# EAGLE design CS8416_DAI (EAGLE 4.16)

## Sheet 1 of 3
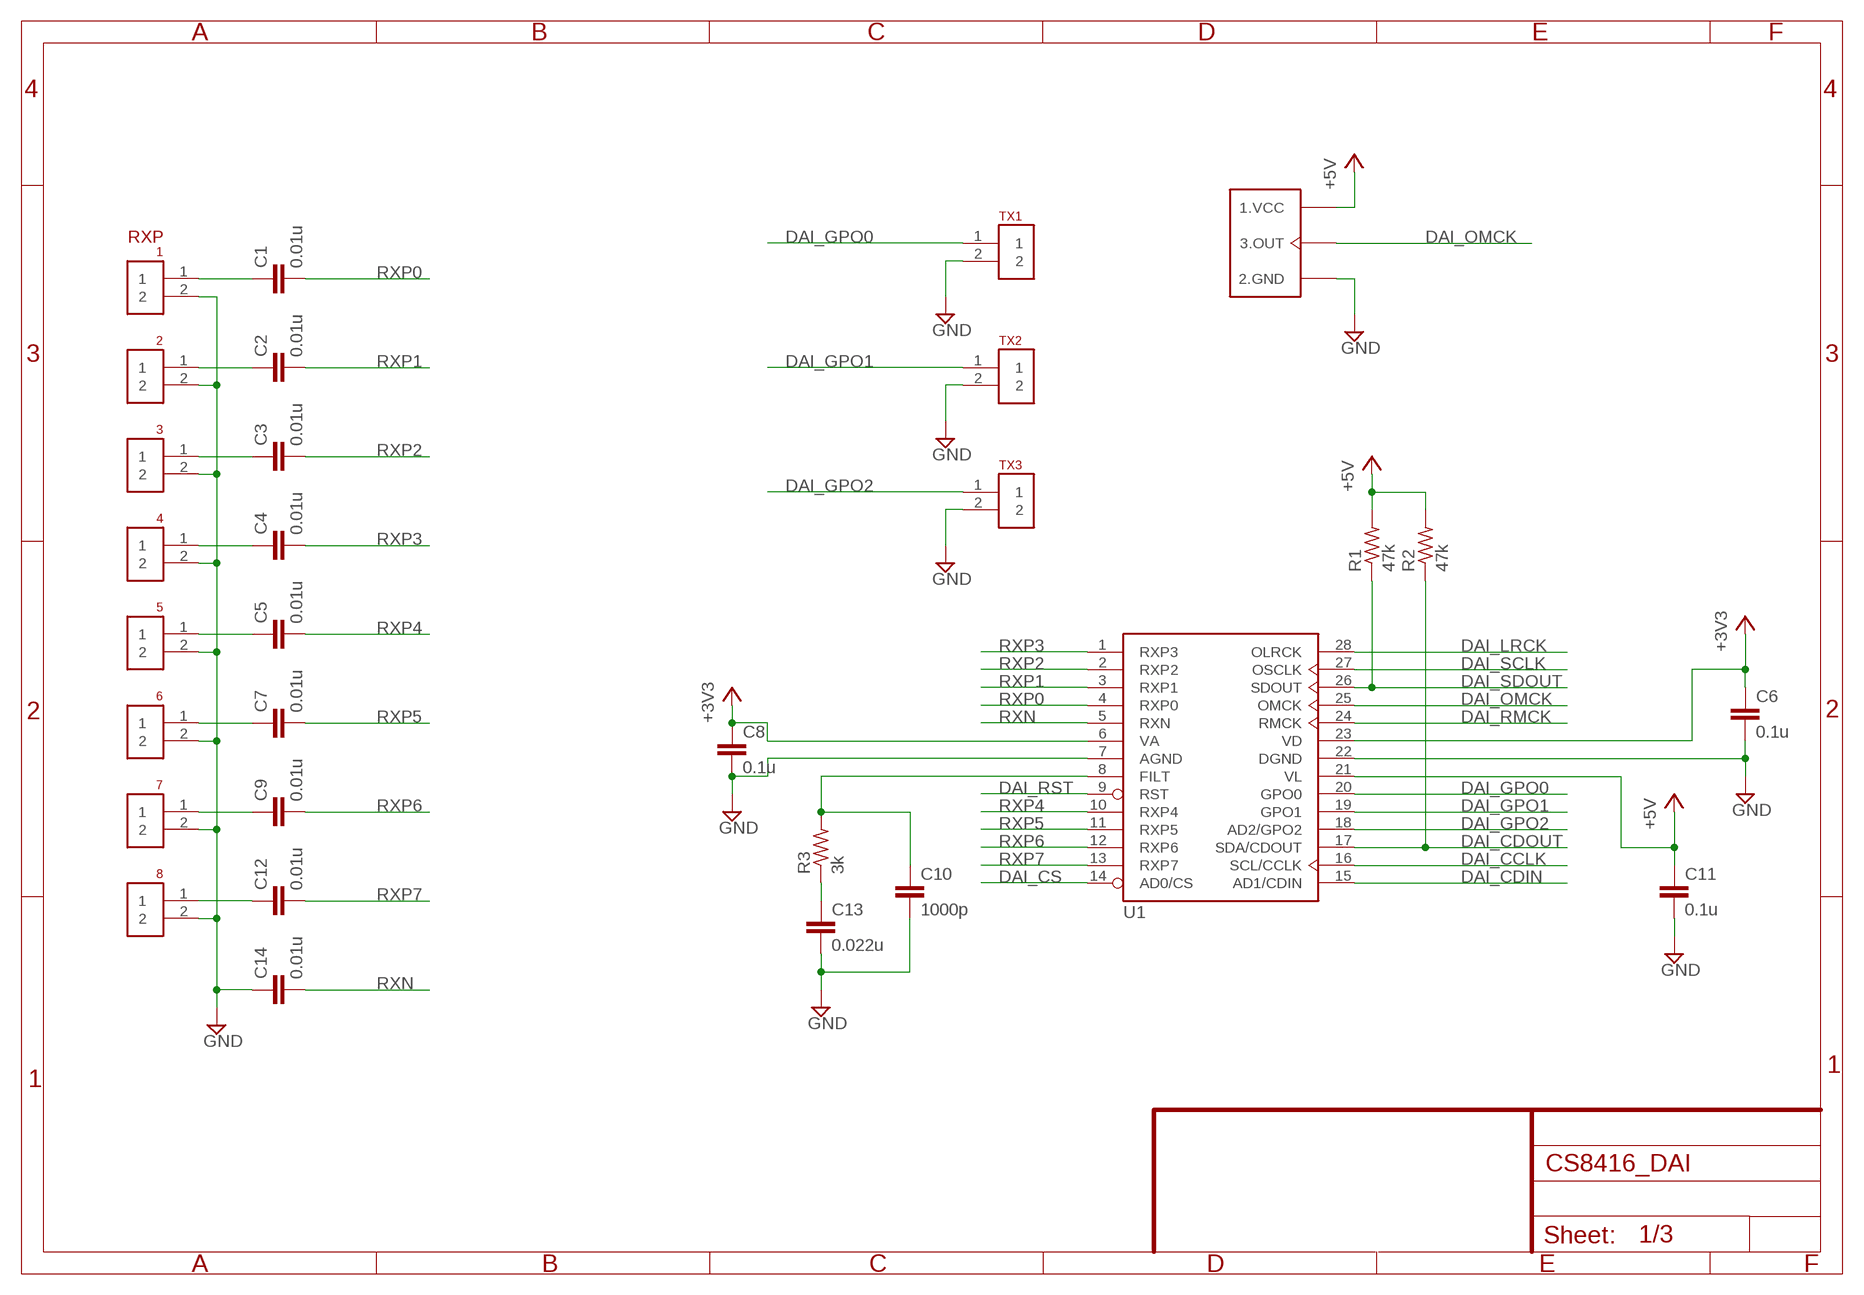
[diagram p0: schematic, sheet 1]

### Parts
1  PINHEADER_1X2  [PINHEADER_1X2]
2  PINHEADER_1X2  [PINHEADER_1X2]
3  PINHEADER_1X2  [PINHEADER_1X2]
4  PINHEADER_1X2  [PINHEADER_1X2]
5  PINHEADER_1X2  [PINHEADER_1X2]
6  PINHEADER_1X2  [PINHEADER_1X2]
7  PINHEADER_1X2  [PINHEADER_1X2]
8  PINHEADER_1X2  [PINHEADER_1X2]
C1  0.01u  C-EU050-024X044  [C050-024X044]
C2  0.01u  C-EU050-024X044  [C050-024X044]
C3  0.01u  C-EU050-024X044  [C050-024X044]
C4  0.01u  C-EU050-024X044  [C050-024X044]
C5  0.01u  C-EU050-024X044  [C050-024X044]
C6  0.1u  C-EU025-024X044  [C025-024X044]
C7  0.01u  C-EU050-024X044  [C050-024X044]
C8  0.1u  C-EU050-024X044  [C050-024X044]
C9  0.01u  C-EU050-024X044  [C050-024X044]
C10  1000p  C-EU050-024X044  [C050-024X044]
C11  0.1u  C-EU025-024X044  [C025-024X044]
C12  0.01u  C-EU050-024X044  [C050-024X044]
C13  0.022u  C-EU050-024X044  [C050-024X044]
C14  0.01u  C-EU050-024X044  [C050-024X044]
R1  47k  R-US_0204/2V  [0204V]
R2  47k  R-US_0204/2V  [0204V]
R3  3k  R-US_0204/2V  [0204V]
TX1  PINHEADER_1X2  [PINHEADER_1X2]
TX2  PINHEADER_1X2  [PINHEADER_1X2]
TX3  PINHEADER_1X2  [PINHEADER_1X2]
U1  CS8416  [SO28-3]
X1  DOC-49S3  [AT-49]

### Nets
+3V3: C6.1 C8.1 U1.6(VA) U1.23(VD) ; also sheet 3
+5V: C11.1 R1.2 R2.2 U1.21(VL) X1.1.VCC ; also sheet 2,3
DAI_CCLK: U1.16(SCL/CCLK) ; also sheet 2
DAI_CDIN: U1.15(AD1/CDIN) ; also sheet 2
DAI_CDOUT: R2.1 U1.17(SDA/CDOUT) ; also sheet 2
DAI_CS: U1.14(AD0/CS) ; also sheet 2
DAI_GPO0: TX1.1 U1.20(GPO0)
DAI_GPO1: TX2.1 U1.19(GPO1)
DAI_GPO2: TX3.1 U1.18(AD2/GPO2)
DAI_LRCK: U1.28(OLRCK) ; also sheet 3
DAI_OMCK: U1.25(OMCK) X1.3.OUT
DAI_RMCK: U1.24(RMCK) ; also sheet 3
DAI_RST: U1.9(RST) ; also sheet 2
DAI_SCLK: U1.27(OSCLK) ; also sheet 3
DAI_SDOUT: R1.1 U1.26(SDOUT) ; also sheet 3
GND: 1.2 2.2 3.2 4.2 5.2 6.2 7.2 8.2 C6.2 C8.2 C10.2 C11.2 C13.2 C14.1 TX1.2 TX2.2 TX3.2 U1.7(AGND) U1.22(DGND) X1.2.GND ; also sheet 2,3
N$1: 8.1 C12.1
N$2: 7.1 C9.1
N$3: 6.1 C7.1
N$4: 5.1 C5.1
N$5: 4.1 C4.1
N$6: 3.1 C3.1
N$7: 2.1 C2.1
N$8: 1.1 C1.1
N$9: C13.1 R3.1
RFLT: C10.1 R3.2 U1.8(FILT)
RXN: C14.2 U1.5(RXN)
RXP0: C1.2 U1.4(RXP0)
RXP1: C2.2 U1.3(RXP1)
RXP2: C3.2 U1.2(RXP2)
RXP3: C4.2 U1.1(RXP3)
RXP4: C5.2 U1.10(RXP4)
RXP5: C7.2 U1.11(RXP5)
RXP6: C9.2 U1.12(RXP6)
RXP7: C12.2 U1.13(RXP7)

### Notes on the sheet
- RXP

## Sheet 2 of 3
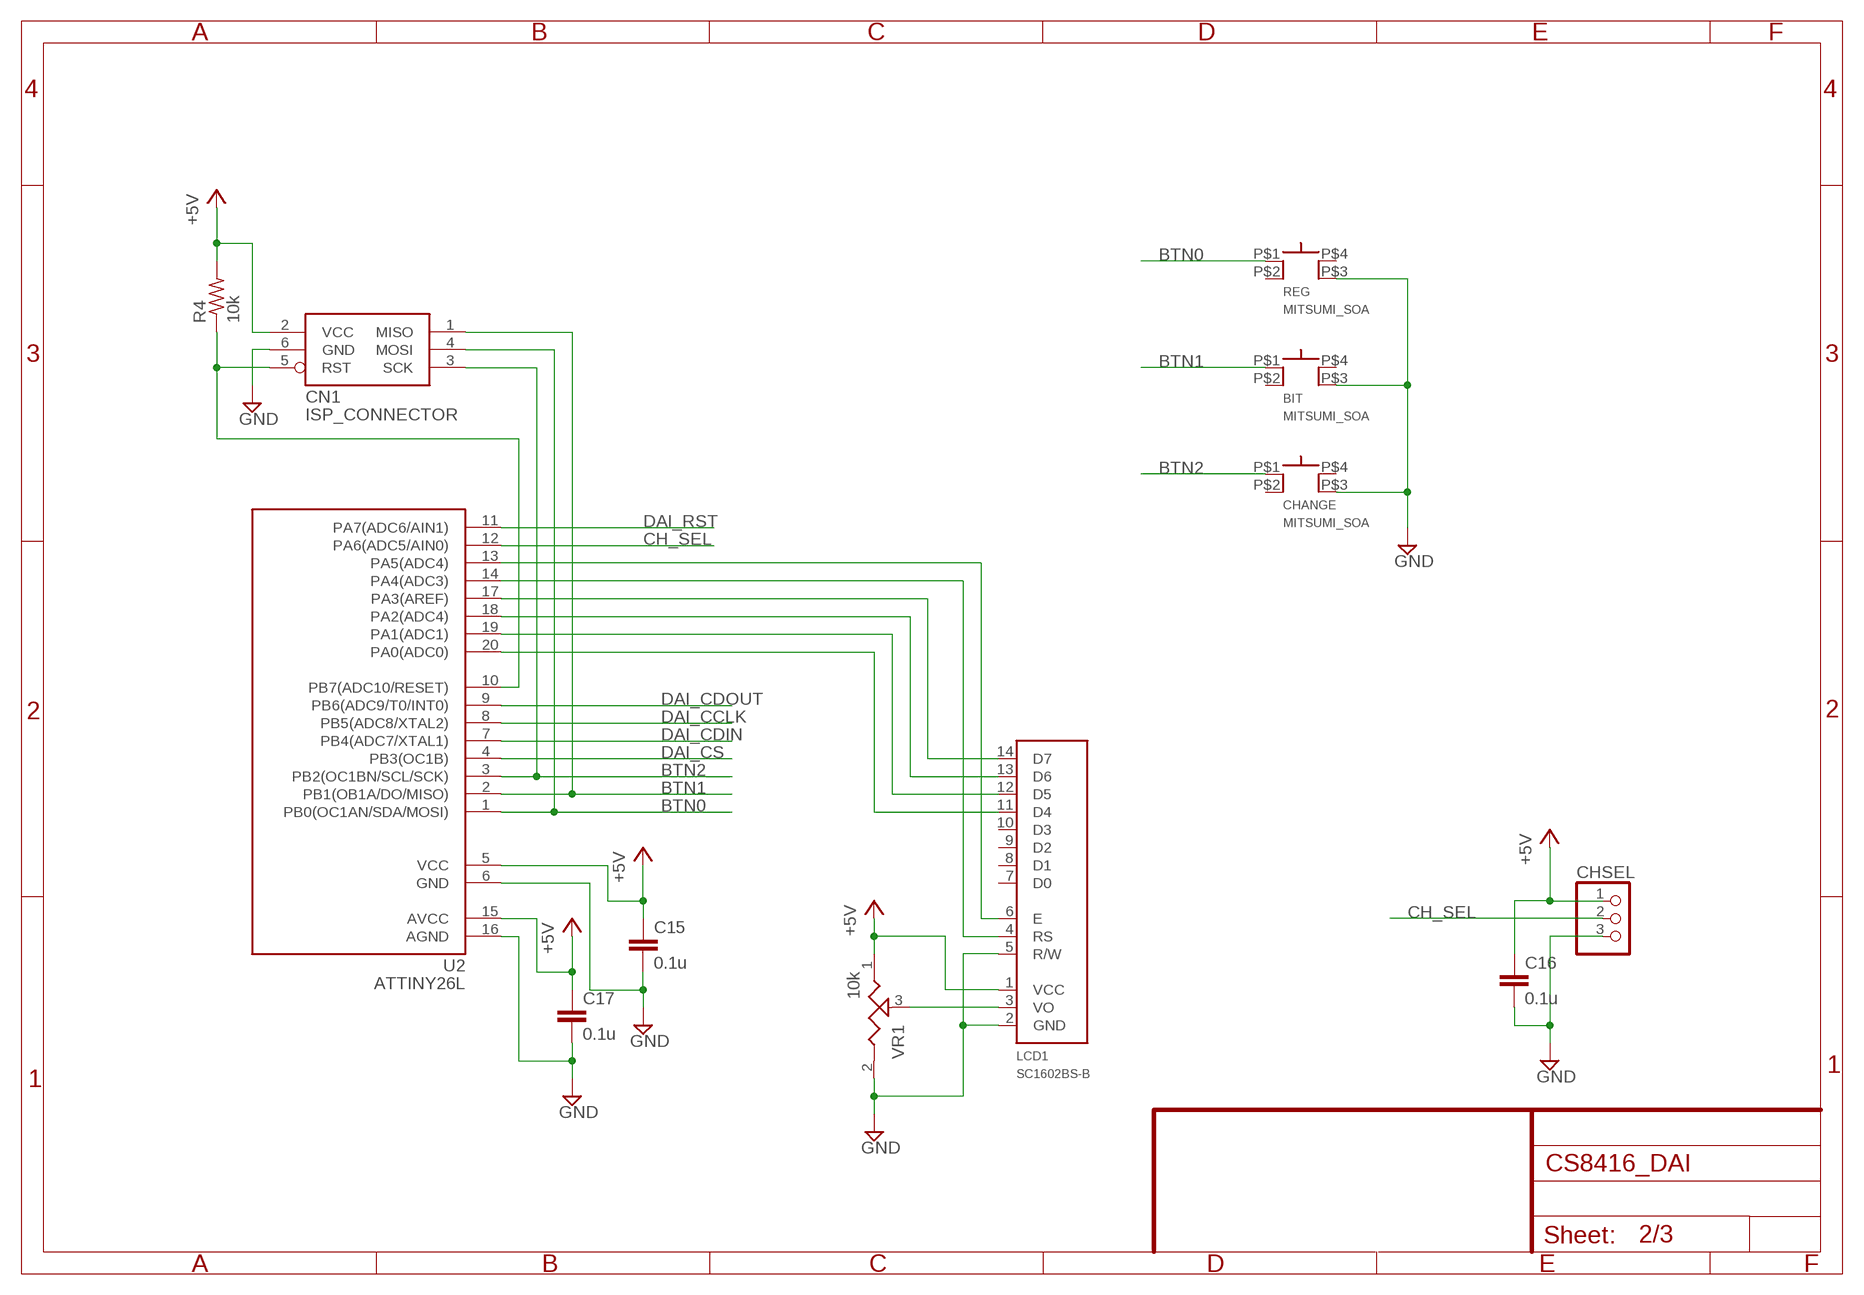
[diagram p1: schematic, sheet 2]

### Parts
BIT  MITSUMI_SOA  [MITSUMI-SOA]
C15  0.1u  C-EU025-024X044  [C025-024X044]
C16  0.1u  C-EU050-024X044  [C050-024X044]
C17  0.1u  C-EU025-024X044  [C025-024X044]
CHANGE  MITSUMI_SOA  [MITSUMI-SOA]
CHSEL  PINHEADER_1X3  [1X03]
CN1  ISP_CONNECTOR  [ISP_CONNECTOR]
LCD1  SC1602BS-B  [SC1602BS-B]
R4  10k  R-US_0204/2V  [0204V]
REG  MITSUMI_SOA  [MITSUMI-SOA]
U2  ATTINY26L  [DIL20]
VR1  10k  VR  [VR]

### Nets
+5V: C15.1 C16.1 C17.1 CHSEL.1 CN1.2(VCC) LCD1.1(VCC) R4.2 U2.5(VCC) U2.15(AVCC) VR1.1 ; also sheet 1,3
BTN0: CN1.4(MOSI) REG.P$1 U2.1(PB0(OC1AN/SDA/MOSI))
BTN1: BIT.P$1 CN1.1(MISO) U2.2(PB1(OB1A/DO/MISO))
BTN2: CHANGE.P$1 CN1.3(SCK) U2.3(PB2(OC1BN/SCL/SCK))
CH_SEL: CHSEL.2 U2.12(PA6(ADC5/AIN0))
DAI_CCLK: U2.8(PB5(ADC8/XTAL2)) ; also sheet 1
DAI_CDIN: U2.7(PB4(ADC7/XTAL1)) ; also sheet 1
DAI_CDOUT: U2.9(PB6(ADC9/T0/INT0)) ; also sheet 1
DAI_CS: U2.4(PB3(OC1B)) ; also sheet 1
DAI_RST: U2.11(PA7(ADC6/AIN1)) ; also sheet 1
GND: BIT.P$3 C15.2 C16.2 C17.2 CHANGE.P$3 CHSEL.3 CN1.6(GND) LCD1.2(GND) LCD1.5(R/W) REG.P$3 U2.6(GND) U2.16(AGND) VR1.2 ; also sheet 1,3
LCD_E: LCD1.6(E) U2.13(PA5(ADC4))
LCD_RS: LCD1.4(RS) U2.14(PA4(ADC3))
N$11: CN1.5(RST) R4.1 U2.10(PB7(ADC10/RESET))
N$13: LCD1.3(VO) VR1.3
N$14: LCD1.11(D4) U2.20(PA0(ADC0))
N$15: LCD1.12(D5) U2.19(PA1(ADC1))
N$23: LCD1.13(D6) U2.18(PA2(ADC4))
N$24: LCD1.14(D7) U2.17(PA3(AREF))
Unconnected: BIT.P$2 BIT.P$4 CHANGE.P$2 CHANGE.P$4 LCD1.7(D0) LCD1.8(D1) LCD1.9(D2) LCD1.10(D3) REG.P$2 REG.P$4

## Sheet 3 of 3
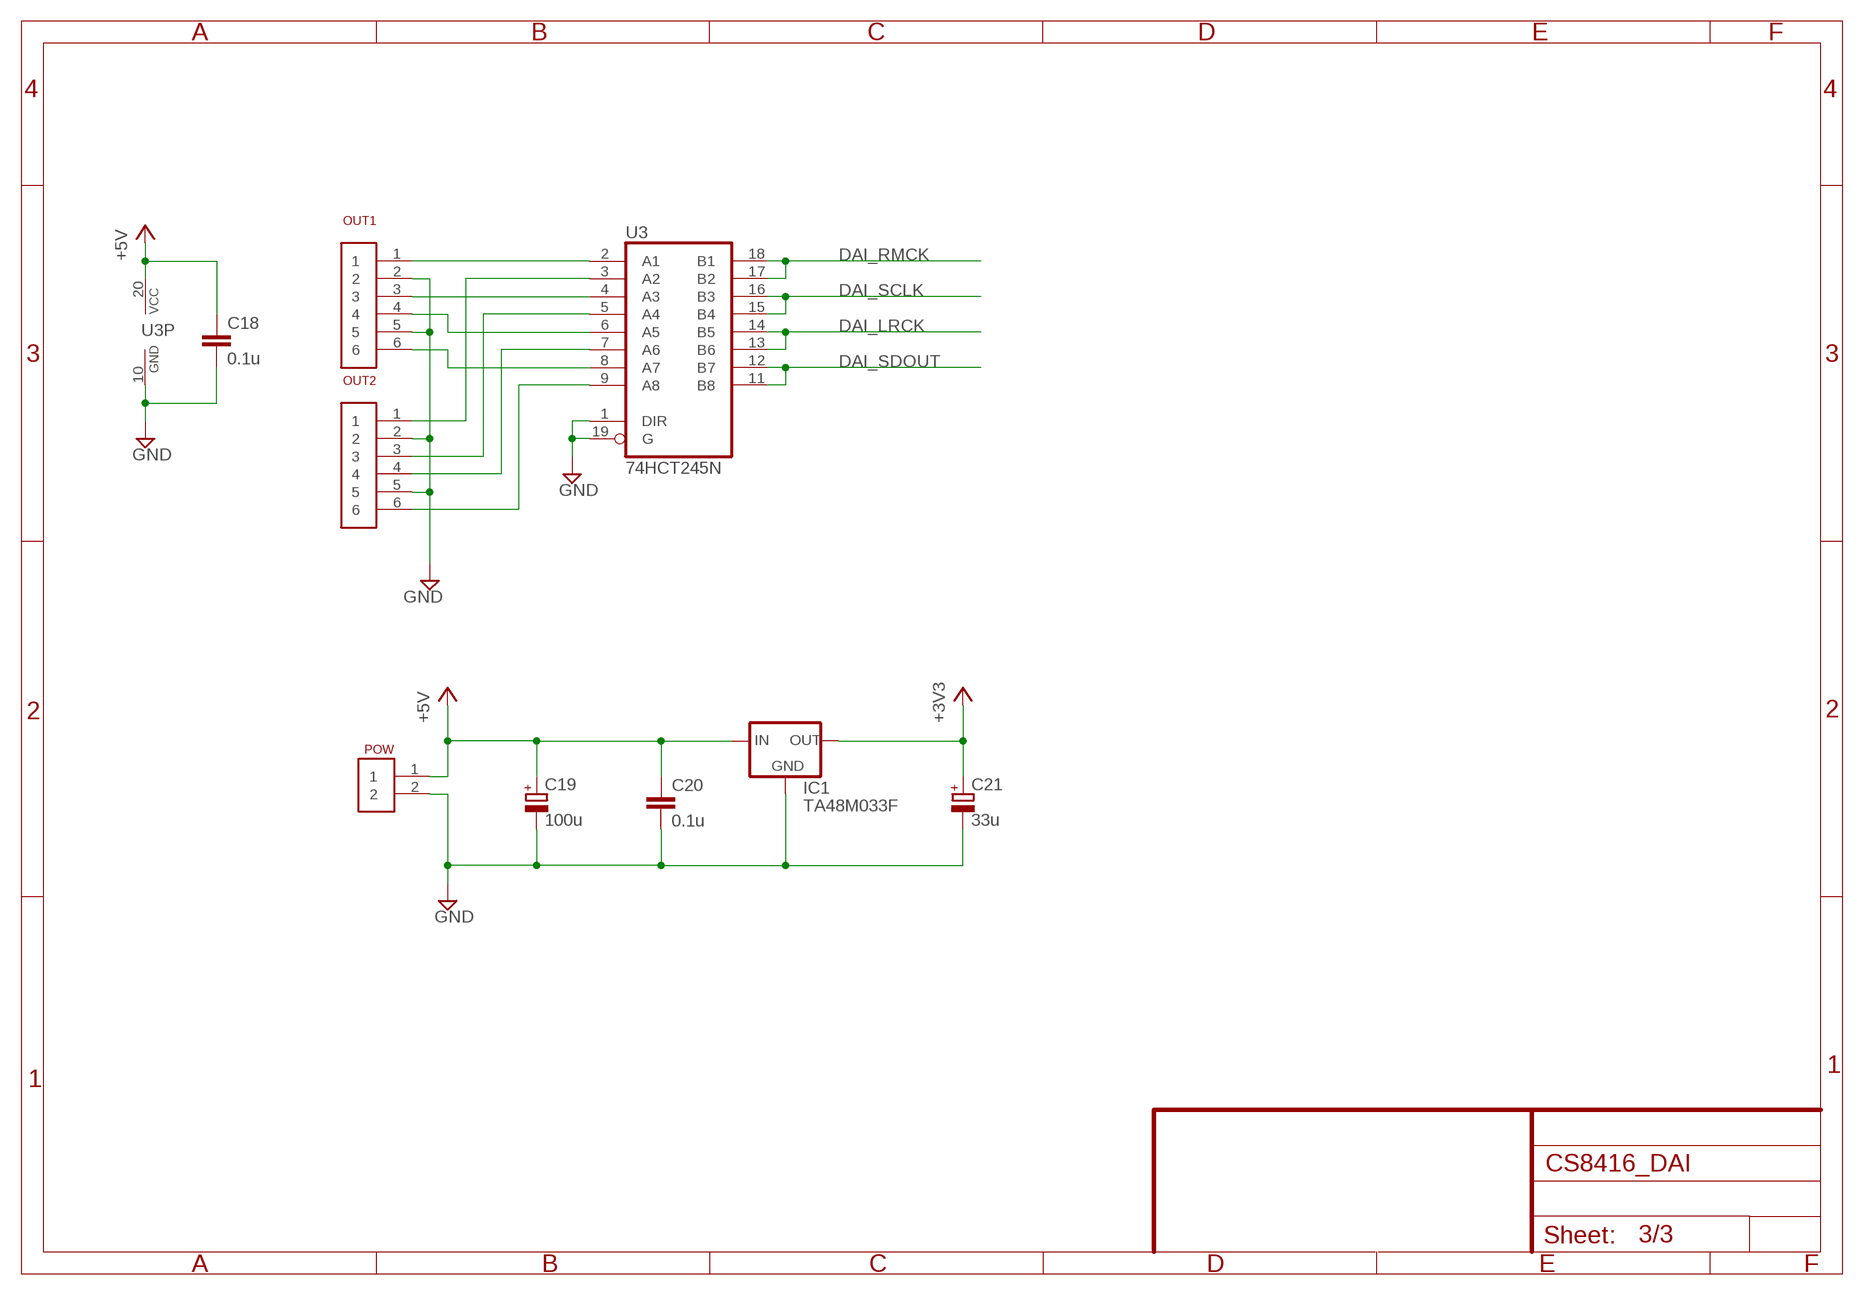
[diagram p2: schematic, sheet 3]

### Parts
C18  0.1u  C-EU050-024X044  [C050-024X044]
C19  100u  CPOL-EUE2.5-6  [E2,5-6]
C20  0.1u  C-EU050-024X044  [C050-024X044]
C21  33u  CPOL-EUE2-5  [E2-5]
IC1  TA48M033F  78MXXS  [78MXXS]
OUT1  PINHEADER_1X6  [PINHEADER_1X6]
OUT2  PINHEADER_1X6  [PINHEADER_1X6]
POW  PINHEADER_1X2  [PINHEADER_1X2]
U3  74HCT245N  [DIL20]

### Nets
+3V3: C21.+ IC1.OUT ; also sheet 1
+5V: C18.1 C19.+ C20.1 IC1.IN POW.1 U3.20(VCC) ; also sheet 1,2
DAI_LRCK: U3.13(B6) U3.14(B5) ; also sheet 1
DAI_RMCK: U3.17(B2) U3.18(B1) ; also sheet 1
DAI_SCLK: U3.15(B4) U3.16(B3) ; also sheet 1
DAI_SDOUT: U3.11(B8) U3.12(B7) ; also sheet 1
GND: C18.2 C19.- C20.2 C21.- IC1.GND OUT1.2 OUT1.5 OUT2.2 OUT2.5 POW.2 U3.1(DIR) U3.10(GND) U3.19(G) ; also sheet 1,2
N$12: OUT1.1 U3.2(A1)
N$16: OUT1.3 U3.4(A3)
N$17: OUT1.4 U3.6(A5)
N$18: OUT1.6 U3.8(A7)
N$19: OUT2.1 U3.3(A2)
N$20: OUT2.3 U3.5(A4)
N$21: OUT2.4 U3.7(A6)
N$22: OUT2.6 U3.9(A8)

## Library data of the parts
1-8 POW TX1-TX3 = CS8416_DAI:PINHEADER_1X2
BIT CHANGE REG = CS8416_DAI:MITSUMI_SOA
C1-C18 C20 = CS8416_DAI:C-EU: CAPACITOR, European symbol
C19 C21 = CS8416_DAI:CPOL-EU: POLARIZED CAPACITOR, European symbol
CHSEL = CS8416_DAI:PINHEADER_1X3: PIN HEADER
CN1 = CS8416_DAI:ISP_CONNECTOR: ISP Connector
IC1 = CS8416_DAI:78MXXS: VOLTAGE REGULATOR
LCD1 = CS8416_DAI:SC1602BS-B: LCD Module SUNLIKE SC1602BS-B
OUT1 OUT2 = CS8416_DAI:PINHEADER_1X6
R1-R4 = CS8416_DAI:R-US_: RESISTOR, American symbol
U1 = CS8416_DAI:CS8416
U2 = CS8416_DAI:ATTINY26L
U3 = CS8416_DAI:74*245: Octal BUS TRANSCEIVER, 3-state
VR1 = CS8416_DAI:VR
X1 = CS8416_DAI:DOC-49S3

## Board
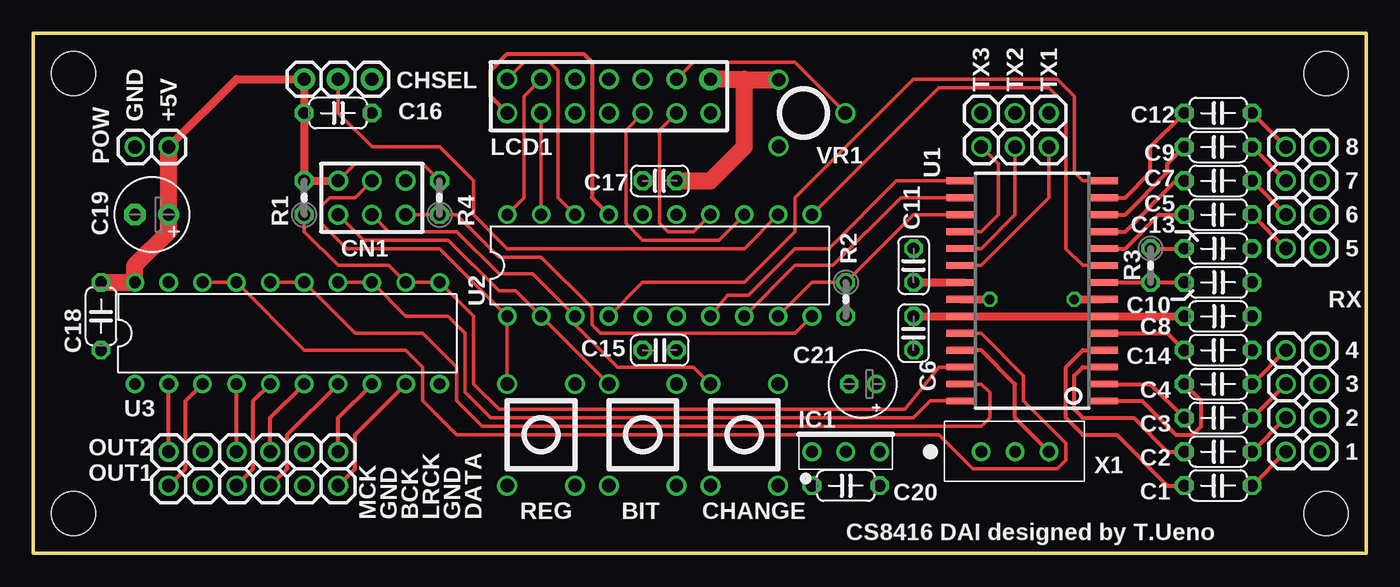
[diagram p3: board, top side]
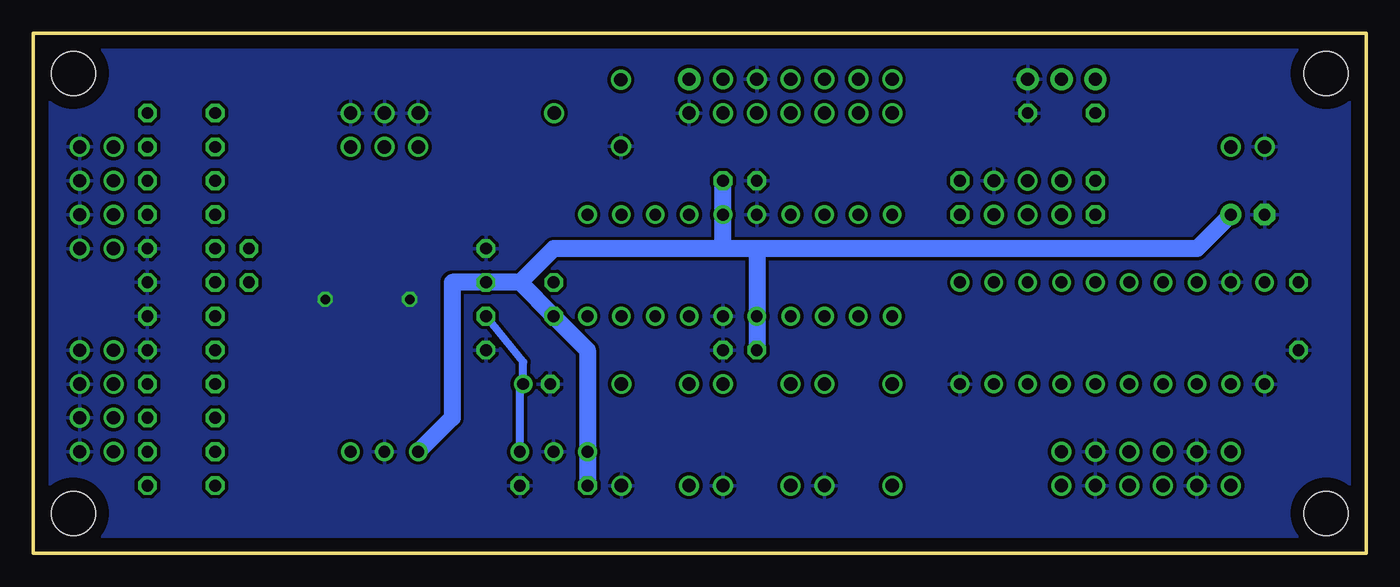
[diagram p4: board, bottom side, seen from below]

Size 100 x 39 mm. Coordinates in mm from the lower left corner, seen from the top.
Outline: 0,0 100,0 100,39 0,39 0,0
Copper layers (1*16): Top 0.035mm / dielectric 1.5mm / Bottom 0.035mm
Design rules "10mils": minimum track width 10mil, minimum drill 24mil, track to track 10mil, track to pad 10mil, pad to pad 10mil, via to via 10mil, smd to smd 10mil, copper to edge 40mil, drill to drill 10mil, minimum pad ring 10mil, minimum via ring 8mil, stop-mask expansion 0mil, vias tented up to drill 0mil, thermal gap 10mil
Holes 3.3 mm at 3,36 3,3 97,3 97,36

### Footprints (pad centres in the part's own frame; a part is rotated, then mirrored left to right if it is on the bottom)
PINHEADER_1X2 = drill 0.991 round: 1 -2.54,0; 2 0,0
MITSUMI-SOA = drill 0.991 round: P$1 -6.35,0; P$2 1.27,0; P$3 1.27,5.08; P$4 -6.35,5.08
C050-024X044 = drill 0.889 octagon: 1 -2.54,0; 2 2.54,0
C025-024X044 = drill 0.889 octagon: 1 -1.27,0; 2 1.27,0
E2,5-6 = drill 0.889 pad 1.6 round: + -1.27,0 | drill 0.889 pad 1.6 octagon: - 1.27,0
E2-5 = drill 0.889 pad 1.27 round: + -1.016,0 | drill 0.889 pad 1.27 octagon: - 1.016,0
1X03 = drill 0.991 pad 1.676 round: 1 -2.54,0; 2 0,0; 3 2.54,0
ISP_CONNECTOR = drill 0.991 round: 1 -1.27,2.54; 2 1.27,2.54; 3 -1.27,0; 4 1.27,0; 5 -1.27,-2.54; 6 1.27,-2.54
78MXXS = drill 0.889 round: GND 0,0; IN -2.54,0; OUT 2.54,0
SC1602BS-B = drill 0.991 pad 1.676 round: 1 1.27,-7.62 | drill 0.991 round: 2 -1.27,-7.62; 3 1.27,-5.08; 4 -1.27,-5.08; 5 1.27,-2.54; 6 -1.27,-2.54; 7 1.27,0; 8 -1.27,0; 9 1.27,2.54; 10 -1.27,2.54; 11 1.27,5.08; 12 -1.27,5.08; 13 1.27,7.62; 14 -1.27,7.62
PINHEADER_1X6 = drill 0.991 round: 1 -7.62,0; 2 -5.08,0; 3 -2.54,0; 4 0,0; 5 2.54,0; 6 5.08,0
0204V = drill 0.889 octagon: 1 -1.27,0; 2 1.27,0
SO28-3 = smd 0.51 x 2.21: 1 -8.255,-5.315; 2 -6.985,-5.315; 3 -5.715,-5.315; 4 -4.445,-5.315; 5 -3.175,-5.315; 6 -1.905,-5.315; 7 -0.635,-5.315; 8 0.635,-5.315; 9 1.905,-5.315; 10 3.175,-5.315; 11 4.445,-5.315; 12 5.715,-5.315; 13 6.985,-5.315; 14 8.255,-5.315; 15 8.255,5.315; 16 6.985,5.315; 17 5.715,5.315; 18 4.445,5.315; 19 3.175,5.315; 20 1.905,5.315; 21 0.635,5.315; 22 -0.635,5.315; 23 -1.905,5.315; 24 -3.175,5.315; 25 -4.445,5.315; 26 -5.715,5.315; 27 -6.985,5.315; 28 -8.255,5.315
DIL20 = drill 0.889 round: 1 -11.43,-3.81; 2 -8.89,-3.81; 3 -6.35,-3.81; 4 -3.81,-3.81; 5 -1.27,-3.81; 6 1.27,-3.81; 7 3.81,-3.81; 8 6.35,-3.81; 9 8.89,-3.81; 10 11.43,-3.81; 11 11.43,3.81; 12 8.89,3.81; 13 6.35,3.81; 14 3.81,3.81; 15 1.27,3.81; 16 -1.27,3.81; 17 -3.81,3.81; 18 -6.35,3.81; 19 -8.89,3.81; 20 -11.43,3.81
VR = drill 0.991 round: 1 -2.5,-3.77; 2 2.5,-3.77; 3 0,1.23
AT-49 = drill 0.889 round: 1.VCC -2.54,0; 2.GND 0,0; 3.OUT 2.54,0

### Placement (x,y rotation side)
1  96.52,7.62 0 top
2  96.52,10.16 0 top
3  96.52,12.7 0 top
4  96.52,15.24 0 top
5  96.52,22.86 0 top
6  96.52,25.4 0 top
7  96.52,27.94 0 top
8  96.52,30.48 0 top
BIT  43.18,6.35 270 top
C1  88.9,5.08 180 top
C2  88.9,7.62 180 top
C3  88.9,10.16 180 top
C4  88.9,12.7 180 top
C5  88.9,25.4 180 top
C6  66.04,16.51 270 top
C7  88.9,27.94 180 top
C8  88.9,17.78 0 top
C9  88.9,30.48 180 top
C10  88.9,20.32 0 top
C11  66.04,21.59 90 top
C12  88.9,33.02 180 top
C13  88.9,22.86 0 top
C14  88.9,15.24 180 top
C15  46.99,15.24 0 top
C16  22.86,33.02 0 top
C17  46.99,27.94 180 top
C18  5.08,17.78 270 top
C19  8.89,25.4 180 top
C20  60.96,5.08 0 top
C21  62.23,12.7 180 top
CHANGE  50.8,6.35 270 top
CHSEL  22.86,35.56 0 top
CN1  25.4,26.67 90 top
IC1  60.96,7.62 0 top
LCD1  43.18,34.29 90 top
OUT1  17.78,7.62 0 top
OUT2  17.78,5.08 0 top
POW  7.62,30.48 180 top
R1  20.32,26.67 90 top
R2  60.96,19.05 270 top
R3  83.82,21.59 270 top
R4  30.48,26.67 90 top
REG  35.56,6.35 270 top
TX1  76.2,33.02 90 top
TX2  73.66,33.02 90 top
TX3  71.12,33.02 90 top
U1  74.93,19.68 90 top
U2  46.99,21.59 0 top
U3  19.05,16.51 0 top
VR1  59.69,33.02 270 top
X1  73.66,7.62 0 top

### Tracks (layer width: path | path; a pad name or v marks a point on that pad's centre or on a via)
+3V3
  Top 0.61: C8.1 U1.6 U1.23 C6.1
  Bottom 0.61: IC1.OUT 63.5,12.45 C21.+ 63.25,14.35 C6.1
+5V
  Top 0.254: CN1.2 24.13,29.21 29.21,29.21 R4.2
  Top 0.61: 69.85,20.32 U1.21 C11.1 | POW.1 15.24,35.56 CHSEL.1 C16.1 R1.2 CN1.2
  Top 1.27: POW.1 C19.+ 10.16,24.13 7.62,21.59 U3.20 C18.1 | 50.84,35.52 LCD1.1 52.07,35.56 52.11,35.52 53.34,35.52 | C17.1 50.8,27.94 53.34,30.48 53.34,35.52 | 53.34,35.52 VR1.1 | 53.34,35.52 53.34,35.56
  Bottom 1.27: C17.1 U2.15 48.26,22.86 | C15.1 U2.5 45.72,22.86 | 48.26,22.86 60.96,22.86 63.5,20.32 | 45.72,22.86 48.26,22.86 | 45.72,22.86 12.7,22.86 C19.+ | X1.1.VCC 68.58,10.16 68.58,20.32 C11.1 63.5,20.32 | 63.5,20.32 R2.2 58.42,15.24 IC1.IN C20.1
BTN0
  Top 0.254: CN1.4 24.13,26.67 22.23,26.67 21.59,26.04 21.59,24.77 23.5,22.86 30.48,22.86 U2.1 REG.P$1
BTN1
  Top 0.254: CN1.1 24.77,23.5 31.11,23.5 34.92,19.68 36.2,19.68 U2.2 BIT.P$1
BTN2
  Top 0.254: CN1.3 26.67,24.13 31.75,24.13 34.92,20.95 37.47,20.95 U2.3 40.64,17.14 43.81,13.97 49.53,13.97 CHANGE.P$1
CH_SEL
  Top 0.254: U2.12 53.34,22.86 35.56,22.86 33.02,25.4 33.02,27.94 30.48,30.48 25.4,30.48 22.86,33.02 CHSEL.2
DAI_CCLK
  Top 0.254: U1.16 65.09,26.67 60.01,21.59 57.15,21.59 U2.8
DAI_CDIN
  Top 0.254: U1.15 64.77,27.94 59.69,22.86 57.15,22.86 53.66,19.37 52.07,19.37 U2.7
DAI_CDOUT
  Top 0.254: U1.17 66.04,25.4 R2.1 58.42,20.32 U2.9
DAI_CS
  Top 0.254: U1.14 78.74,27.94 78.11,28.57 78.11,34.29 76.83,35.56 66.04,35.56 57.15,26.67 57.15,24.13 53.34,20.32 45.72,20.32 U2.4
DAI_GPO0
  Top 0.254: U1.20 71.12,21.59 76.2,26.67 TX1.1
DAI_GPO1
  Top 0.254: U1.19 71.12,22.86 73.66,25.4 TX2.1
DAI_GPO2
  Top 0.254: TX3.1 72.39,29.21 72.39,25.4 71.12,24.13 U1.18
DAI_LRCK
  Top 0.254: U3.14 U3.13 27.94,17.78 31.11,17.78 32.38,16.51 32.38,12.06 34.29,10.16 66.04,10.16 67.31,11.43 U1.28
DAI_OMCK
  Top 0.305: U1.25 71.12,15.24 73.66,12.7 73.66,10.16 X1.3.OUT
DAI_RMCK
  Top 0.254: U3.18 U3.17 20.32,15.24 27.94,15.24 29.21,13.97 29.21,11.43 31.75,8.89 67.94,8.89 70.48,6.35 76.83,6.35 77.47,6.99 77.47,8.26 74.3,11.43 74.3,13.34 71.12,16.51 U1.24
DAI_RST
  Top 0.254: U1.9 78.74,21.59 77.47,22.86 77.47,33.66 76.2,34.92 67.94,34.92 U2.11
DAI_SCLK
  Top 0.254: U3.16 U3.15 24.13,16.51 29.21,16.51 31.75,13.97 31.75,11.43 33.66,9.53 71.12,9.53 71.75,10.16 71.75,12.06 71.12,12.7 U1.27 69.22,12.7
DAI_SDOUT
  Top 0.254: R1.1 20.32,24.13 22.86,21.59 26.67,21.59 U3.12 U3.11 33.02,17.78 33.02,12.7 34.92,10.79 65.41,10.79 67.94,13.97 U1.26 69.85,13.97
GND  (via drill 0.71)
  Top 0.61: U1.22 v71.75,19.05 | v78.11,19.05 U1.7
  pour Bottom (isolate 0.254): 0,38.73 0,0 100.33,0 100.33,38.73
LCD_E
  Top 0.254: LCD1.6 44.45,31.75 44.45,24.77 45.72,23.5 51.44,23.5 U2.13
LCD_RS
  Top 0.254: LCD1.4 46.99,31.75 46.99,24.77 47.62,24.13 49.53,24.13 U2.14
N$1
  Top 0.305: C12.1 8.1
N$2
  Top 0.305: C9.1 7.1
N$3
  Top 0.305: C7.1 6.1
N$4
  Top 0.305: C5.1 5.1
N$5
  Top 0.305: C4.1 4.1
N$6
  Top 0.305: C3.1 3.1
N$7
  Top 0.305: C2.1 2.1
N$8
  Top 0.305: C1.1 1.1
N$9
  Top 0.305: R3.1 C13.1
N$11
  Top 0.254: CN1.5 R4.1 31.75,25.4 34.92,22.23 38.1,22.23 41.91,18.41 41.91,17.14 42.55,16.51 57.15,16.51 U2.10
N$12
  Top 0.305: OUT1.1 U3.2
N$13
  Top 0.254: VR1.3 60.92,33.06 57.15,36.83 49.53,36.83 LCD1.3
N$14
  Top 0.254: LCD1.11 36.83,34.29 36.83,26.67 U2.20
N$15
  Top 0.254: U2.19 LCD1.12
N$16
  Top 0.305: OUT1.3 U3.4
N$17
  Top 0.305: U3.6 17.78,10.16 OUT1.4
N$18
  Top 0.305: U3.8 22.86,10.16 OUT1.6
N$19
  Top 0.305: U3.3 11.43,11.43 11.43,6.35 OUT2.1
N$20
  Top 0.305: U3.5 16.51,11.43 16.51,6.35 OUT2.3
N$21
  Top 0.305: U3.7 19.05,8.89 19.05,6.35 OUT2.4
N$22
  Top 0.305: U3.9 24.13,8.89 24.13,6.35 OUT2.6
N$23
  Top 0.254: LCD1.13 36.83,36.83 38.73,36.83 39.37,36.2 39.37,26.67 U2.18
N$24
  Top 0.305: U2.17 41.91,26.67 41.91,36.83 41.27,37.47 35.56,37.47 34.29,36.2 34.29,34.29 LCD1.14
RFLT
  Top 0.305: C10.1 R3.2 U1.8
RXN
  Top 0.305: U1.5 85.09,16.51 C14.2
RXP0
  Top 0.305: U1.4 78.74,15.24 77.47,13.97 77.47,10.16 78.74,8.89 81.28,8.89 85.09,5.08 C1.2
RXP1
  Top 0.305: U1.3 78.74,13.97 78.11,13.34 78.11,10.79 78.74,10.16 82.55,10.16 85.09,7.62 C2.2
RXP2
  Top 0.305: U1.2 83.82,12.7 C3.2
RXP3
  Top 0.305: U1.1 83.19,11.43 85.72,8.89 87,8.89 87.63,9.53 87.63,11.43 C4.2
RXP4
  Top 0.305: U1.10 81.92,22.86 84.45,25.4 C5.2
RXP5
  Top 0.305: U1.11 81.92,24.13 85.72,27.94 C7.2
RXP6
  Top 0.305: U1.12 81.92,25.4 85.09,28.57 85.09,29.21 C9.2
RXP7
  Top 0.305: U1.13 81.92,26.67 83.82,28.57 83.82,30.48 C12.2

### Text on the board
tPlace: GND | +5V | RX | MCK | GND | BCK | LRCK | GND | DATA | CS8416 DAI designed by T.Ueno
